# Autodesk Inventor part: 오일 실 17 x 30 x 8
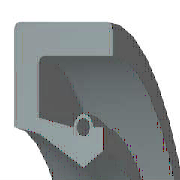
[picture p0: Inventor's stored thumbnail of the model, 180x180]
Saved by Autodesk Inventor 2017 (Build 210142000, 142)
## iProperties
IsCustomPart: 0
Created: 2016-05
Part Number: 오일 실 17 x 30 x 8
Material: 고무
Description: 오일-실
Document SubType Name: Modeling
Standard: KS B 2804
Designer: mduedu
Standards Organization: KS
Language: ko-KR
Size Designation: S - 17 30 8
Categories: <MemberInstance><Categories><Category DisplayName="샤프트 부품" InternalName="7f7aeb1f-a693-4053-b835-cee3144e0d98" Mnemonic="SHFT"><Category DisplayName="실링" Intern
Density: 0.93 g/cm^3
Appearance: 고무 - 검은색 - 버전 1.1
Author: mduedu
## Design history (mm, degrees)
revolve "본체" stored, may be unused: angle "d17" = 90 deg
revolve "스프링1" stored, may be unused: angle "d18" = 90 deg
body "Solid1"
sketch "스케치1"
  geometry: L1 (0, 15)-(8, 15); L2 (8, 15)-(8, 13.75); L3 (8, 13.75)-(1.75, 13.75); L4 (0, 15)-(0, 10.6); L5 (0, 10.6)-(1.75, 10.25); L6 (1.75, 10.25)-(4.9, 8.5); L7 (4.9, 8.5)-(0, 8.5); L8 (6.3, 9.375)-(6.3, 10.6); L9 (0, 0)-(9.586, 0) reference; L10 (4.9, 8.5)-(6.3, 9.375); L11 (0, 18)-(0, -3) reference; L12 (-1.917, 0)-(11.503, 0) reference; L13 (4.2, 10.6)-(1.75, 11.09); L14 (1.75, 11.09)-(1.75, 13.75); L15 (6.3, 10.6)-(5.6, 10.6); C1 r 0.455 at (4.9, 10.6); A1 r 0.7 centre (4.9, 10.6) between (5.6, 10.6) and (4.2, 10.6)
  constraints: 26 end point, 5 horizontal alignment, 4 perpendicular, 2 centre point, 2 collinear, 2 horizontal, 2 parallel, 2 point on circle, 2 point on line, 2 vertical alignment, 1 coincident
  dimensions: "d0" = 30 diameter of L1 L9 (= SD2); "d1" = 18.75 diameter of L8.start L9 (= ABDM); "d2" = 1.25 distance of L1.end L2.end (computed from SD); "d3" = 0.91 diameter of C1 (= SPDI); "d4" = 1.4 diameter of A1 (= SPDA); "d5" = 17 diameter of L6.end L9 (= NND); "d6" = 20.5 diameter of L5.end L9 (= TKDM); "d7" = 21.2 diameter of L4.end L9 (= HLDM); "d8" = 4.9 distance from line of C1.centre L4 (= SPDST); "d9" = 6.3 distance between parallel lines of L8 L4 (= SDI); "d10" = 8 distance between parallel lines of L2 L4 (= SWDT); "d12" = 1.75 distance between parallel lines of L14 L4 (= SD)
fillet "모깎기1" dims "d11" = 0.3 (= RR)
other parameters: "SD2" = 30 [user parameter; used in 1 equation term], "SWDT" = 8 [user parameter; used in 1 equation term], "RR" = 0.3 [user parameter; used in 1 equation term], "SD" = 1.75 [user parameter; used in 2 equation terms], "NND" = 17 [user parameter; used in 1 equation term], "SPDA" = 1.4 [user parameter; used in 1 equation term], "SPDI" = 0.91 [user parameter; used in 1 equation term], "TKDM" = 20.5 [user parameter; used in 1 equation term], "HLDM" = 21.2 [user parameter; used in 1 equation term], "ABDM" = 18.75 [user parameter; used in 1 equation term], "SDI" = 6.3 [user parameter; used in 1 equation term], "SPDST" = 4.9 [user parameter; used in 1 equation term], "d13" = 0, "d14" = 0, "d15" = 0, "LAB" = 0.35 [user parameter]
